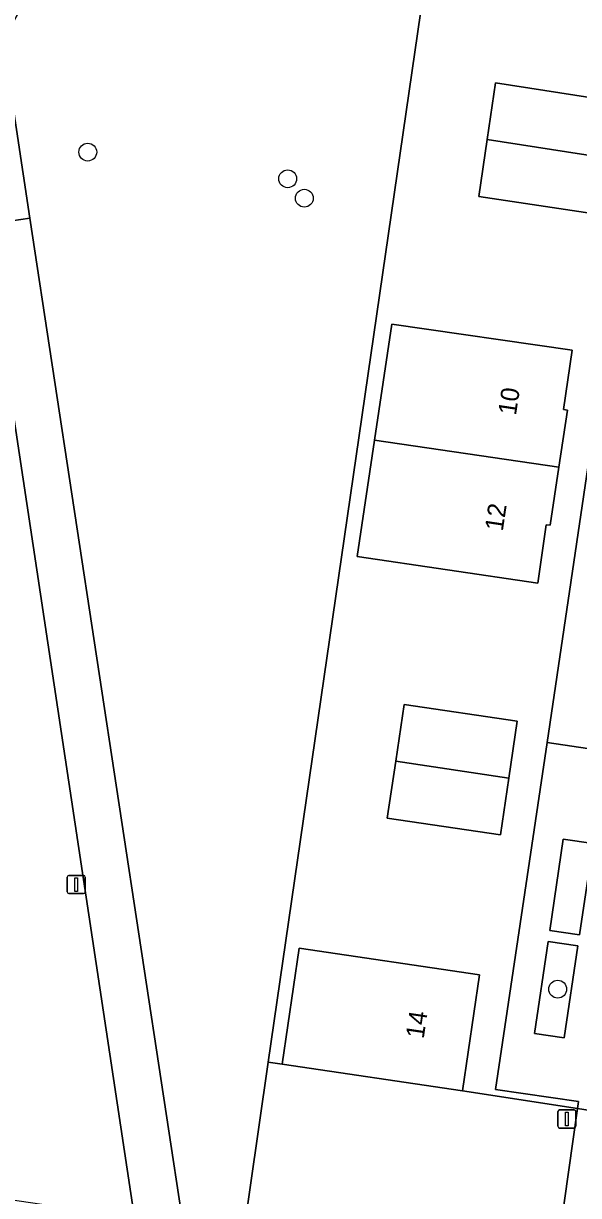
# Model space of a CAD drawing. Extents: x 164148 to 165261, y 382513 to 383432.
# Drawn here: x 164365.5 to 164395.9, y 383053.9 to 383118.2 of the extents above; entities that cross this region are included whole.
import ezdxf

# ---------------------------------------------------------------- set-up
doc = ezdxf.new("R2010")
doc.units = 0
for name, color, linetype in [('IMGEO_Boom', 7, 'Continuous'), ('IMGEO_Erf', 7, 'Continuous'), ('IMGEO_Fietspad_gesloten', 7, 'Continuous'), ('IMGEO_Groenvoorziening', 7, 'Continuous'), ('IMGEO_Lichtmast', 7, 'Continuous'), ('IMGEO_Pand', 7, 'Continuous'), ('IMGEO_Pand_nummerreeks', 7, 'Continuous'), ('IMGEO_Parkeervlak_open', 7, 'Continuous'), ('IMGEO_Verkeersbordpaal', 7, 'Continuous'), ('IMGEO_Voetgangersgebied_open', 7, 'Continuous'), ('IMGEO_Voetpad_gesloten', 7, 'Continuous'), ('IMGEO_Voetpad_open', 7, 'Continuous')]:
    doc.layers.add(name, color=color, linetype=linetype)

msp = doc.modelspace()

# ---------------------------------------------------------------- linework, layer by layer
at = {"layer": 'IMGEO_Boom'}
for centre in [(164369.019, 383111.1), (164379.979, 383109.637), (164380.89, 383108.57), (164394.78, 383065.203)]:
    msp.add_circle(centre, 0.489, dxfattribs=at)
at = {"layer": 'IMGEO_Erf'}
msp.add_lwpolyline([(164408.851, 383199.365), (164399.172, 383200.803), (164378.916, 383061.2), (164379.681, 383061.088), (164380.615, 383067.448), (164390.499, 383065.99), (164389.565, 383059.634), (164395.869, 383058.657), (164395.922, 383059.034), (164391.378, 383059.698), (164394.192, 383078.726), (164411.436, 383195.306)], dxfattribs=at)
for points in [[(164397.596, 383113.926), (164397.135, 383110.828), (164396.675, 383107.73), (164390.464, 383108.674), (164390.918, 383111.782), (164391.372, 383114.89)], [(164395.563, 383100.237), (164395.089, 383096.983), (164395.307, 383096.951), (164394.84, 383093.817), (164394.367, 383090.639), (164394.15, 383090.657), (164393.685, 383087.456), (164383.787, 383088.923), (164384.736, 383095.312), (164385.681, 383101.671)], [(164392.559, 383079.894), (164392.098, 383076.778), (164391.637, 383073.662), (164385.437, 383074.578), (164385.898, 383077.695), (164386.359, 383080.811)]]:
    msp.add_lwpolyline(points, close=True, dxfattribs=at)
at = {"layer": 'IMGEO_Fietspad_gesloten'}
msp.add_lwpolyline([(164397.822, 383058.341), (164395.869, 383058.657), (164394.396, 383048.32), (164396.385, 383048.006)], close=True, dxfattribs=at)
at = {"layer": 'IMGEO_Groenvoorziening'}
for points in [[(164384.016, 383152.889), (164372.909, 383132.94), (164364.381, 383117.193), (164365.844, 383107.485), (164374.414, 383051.19), (164377.4, 383050.755), (164378.916, 383061.2), (164399.172, 383200.803), (164390.354, 383202.053), (164390.119, 383199.218), (164386.886, 383161.611)], [(164254.571, 383078.324), (164255.594, 383087.219), (164253.324, 383078.548), (164251.222, 383070.415), (164371.573, 383052.659), (164363.352, 383107.117), (164359.03, 383106.478), (164362.538, 383089.476), (164360.08, 383065.785)]]:
    msp.add_lwpolyline(points, dxfattribs=at)
for points in [[(164395.126, 383062.534), (164395.878, 383067.578), (164394.251, 383067.821), (164393.499, 383062.777)], [(164379.681, 383061.088), (164378.916, 383061.2), (164377.4, 383050.755), (164393.173, 383048.461), (164394.396, 383048.32), (164395.869, 383058.657), (164389.565, 383059.634)]]:
    msp.add_lwpolyline(points, close=True, dxfattribs=at)
at = {"layer": 'IMGEO_Lichtmast'}
for p, q in [((164367.888, 383070.539), (164367.888, 383071.339)), ((164367.888, 383071.339), (164367.888, 383070.539)), ((164367.988, 383071.439), (164368.778, 383071.439)), ((164368.778, 383071.439), (164367.988, 383071.439)), ((164368.878, 383071.339), (164368.878, 383070.539)), ((164368.878, 383070.539), (164368.878, 383071.339)), ((164368.778, 383070.439), (164367.988, 383070.439)), ((164367.988, 383070.439), (164368.778, 383070.439))]:
    msp.add_line(p, q, dxfattribs=at)
msp.add_lwpolyline([(164368.308, 383071.314), (164368.458, 383071.314), (164368.458, 383070.564), (164368.308, 383070.564), (164368.308, 383071.314)], dxfattribs=at)
for centre, start, end in [((164367.988, 383071.339), 90, 180), ((164367.988, 383071.339), 90, 180), ((164368.778, 383071.339), 0, 90), ((164368.778, 383071.339), 360, 90), ((164367.988, 383070.539), 180, 270), ((164367.988, 383070.539), 180, 270), ((164368.778, 383070.539), 270, 0), ((164368.778, 383070.539), 270, 0)]:
    msp.add_arc(centre, 0.1, start, end, dxfattribs=at)
at = {"layer": 'IMGEO_Pand'}
for points in [[(164390.918, 383111.782), (164397.135, 383110.828), (164397.596, 383113.926), (164391.372, 383114.89)], [(164390.918, 383111.782), (164390.464, 383108.674), (164396.675, 383107.73), (164397.135, 383110.828)], [(164394.84, 383093.817), (164395.307, 383096.951), (164395.089, 383096.983), (164395.563, 383100.237), (164385.681, 383101.671), (164384.736, 383095.312)], [(164394.84, 383093.817), (164384.736, 383095.312), (164383.787, 383088.923), (164393.685, 383087.456), (164394.15, 383090.657), (164394.367, 383090.639)], [(164392.098, 383076.778), (164392.559, 383079.894), (164386.359, 383080.811), (164385.898, 383077.695)], [(164392.098, 383076.778), (164385.898, 383077.695), (164385.437, 383074.578), (164391.637, 383073.662)], [(164389.565, 383059.634), (164390.499, 383065.99), (164380.615, 383067.448), (164379.681, 383061.088)]]:
    msp.add_lwpolyline(points, close=True, dxfattribs=at)
at = {"layer": 'IMGEO_Parkeervlak_open'}
msp.add_lwpolyline([(164395.967, 383068.172), (164396.717, 383073.186), (164395.08, 383073.431), (164394.339, 383068.414)], close=True, dxfattribs=at)
at = {"layer": 'IMGEO_Verkeersbordpaal'}
for p, q in [((164394.786, 383057.687), (164394.786, 383058.487)), ((164394.786, 383058.487), (164394.786, 383057.687)), ((164394.886, 383058.587), (164395.676, 383058.587)), ((164395.676, 383058.587), (164394.886, 383058.587)), ((164395.776, 383058.487), (164395.776, 383057.687)), ((164395.776, 383057.687), (164395.776, 383058.487)), ((164395.676, 383057.587), (164394.886, 383057.587)), ((164394.886, 383057.587), (164395.676, 383057.587))]:
    msp.add_line(p, q, dxfattribs=at)
msp.add_lwpolyline([(164395.206, 383058.462), (164395.356, 383058.462), (164395.356, 383057.712), (164395.206, 383057.712), (164395.206, 383058.462)], dxfattribs=at)
for centre, start, end in [((164394.886, 383058.487), 90, 180), ((164394.886, 383058.487), 90, 180), ((164395.676, 383058.487), 0, 90), ((164395.676, 383058.487), 360, 90), ((164394.886, 383057.687), 180, 270), ((164394.886, 383057.687), 180, 270), ((164395.676, 383057.687), 270, 0), ((164395.676, 383057.687), 270, 0)]:
    msp.add_arc(centre, 0.1, start, end, dxfattribs=at)
at = {"layer": 'IMGEO_Voetgangersgebied_open'}
msp.add_lwpolyline([(164363.352, 383107.117), (164365.844, 383107.485), (164364.381, 383117.193), (164372.909, 383132.94), (164370.838, 383134.54), (164365.771, 383138.455), (164365.254, 383138.523)], dxfattribs=at)
at = {"layer": 'IMGEO_Voetpad_gesloten'}
msp.add_lwpolyline([(164374.414, 383051.19), (164365.844, 383107.485), (164363.352, 383107.117), (164371.573, 383052.659), (164371.722, 383051.672)], close=True, dxfattribs=at)
at = {"layer": 'IMGEO_Voetpad_open'}
msp.add_lwpolyline([(164411.436, 383195.306), (164394.192, 383078.726), (164404.649, 383077.179), (164406.174, 383076.848), (164416.488, 383075.314), (164419.302, 383074.895), (164421.248, 383074.597), (164436.915, 383072.291), (164449.7, 383070.397), (164451.274, 383070.164), (164461.739, 383068.623), (164479.002, 383185.851)], dxfattribs=at)
for points in [[(164404.649, 383077.179), (164394.192, 383078.726), (164391.378, 383059.698), (164395.922, 383059.034), (164395.869, 383058.657), (164397.822, 383058.341), (164397.879, 383058.748), (164401.814, 383058.173)], [(164395.967, 383068.172), (164394.339, 383068.414), (164395.08, 383073.431), (164396.717, 383073.186)], [(164395.126, 383062.534), (164393.499, 383062.777), (164394.251, 383067.821), (164395.878, 383067.578)]]:
    msp.add_lwpolyline(points, close=True, dxfattribs=at)

# ---------------------------------------------------------------- texts
at = {"layer": 'IMGEO_Pand_nummerreeks'}
for s, rotation, p in [('10', 81.48636, (164392.489, 383096.635)), ('12', 81.48636, (164391.766, 383090.282)), ('14', 81.63644, (164387.432, 383062.454))]:
    msp.add_text(s, height=1, rotation=rotation, dxfattribs=at).set_placement(p)

doc.saveas('drawing.dxf')
